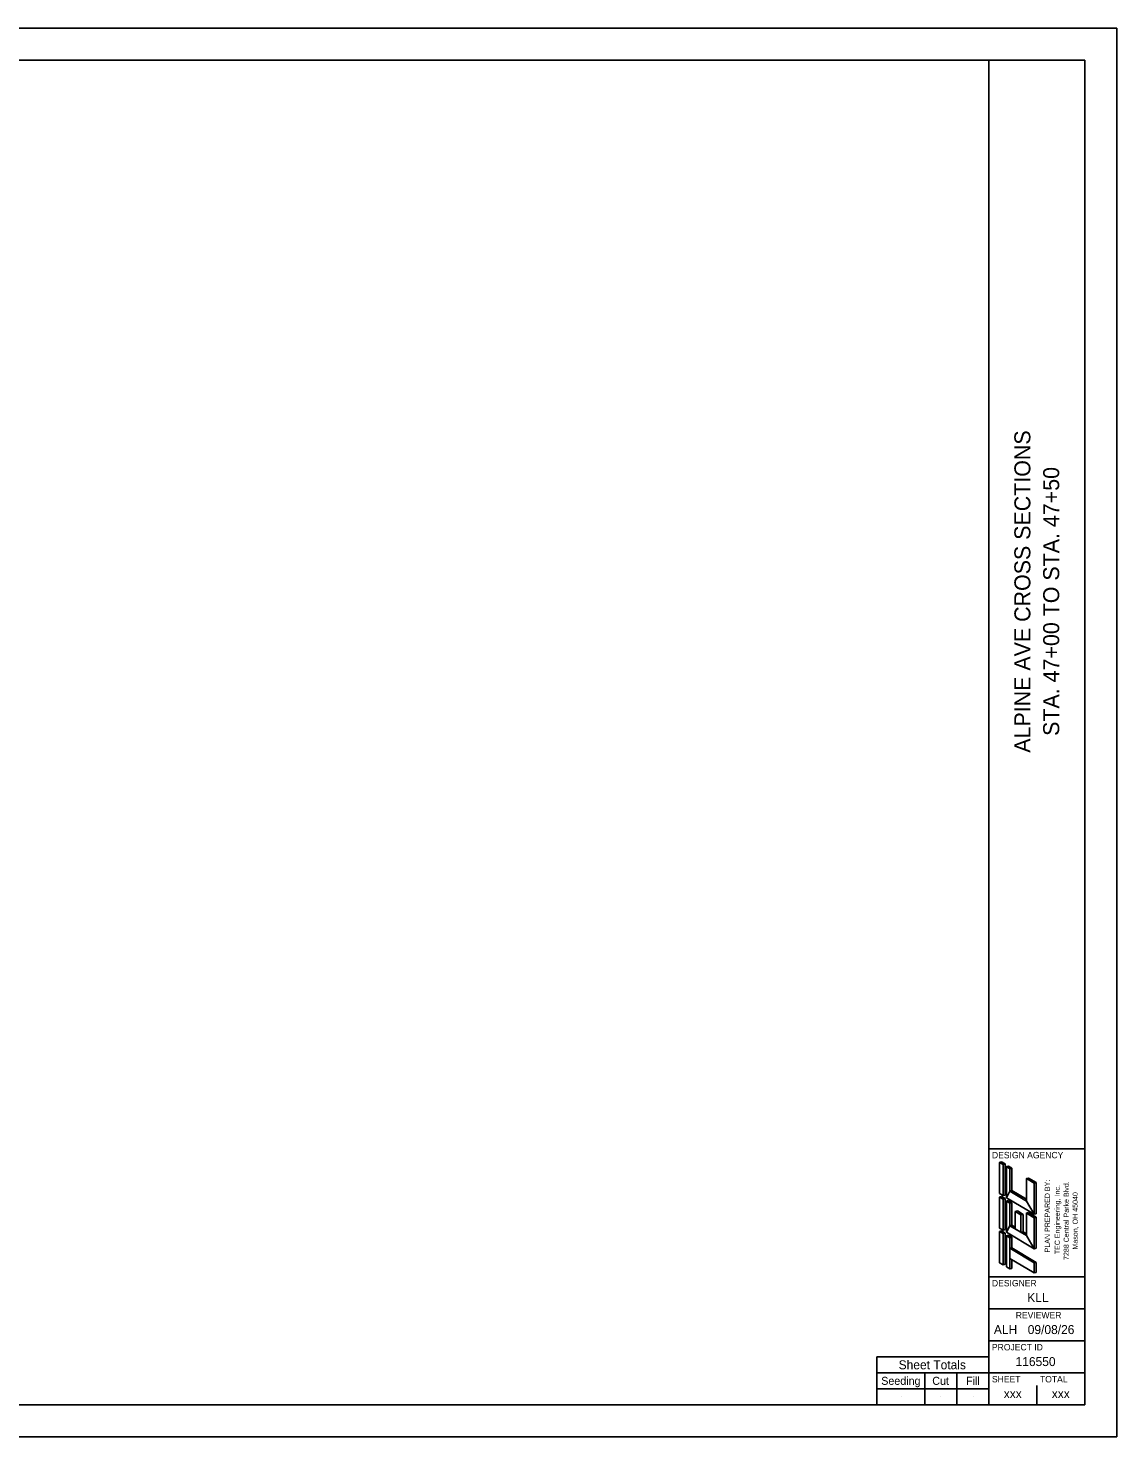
# Model space of a CAD drawing. Extents: x -32.4 to 34, y 0 to 22.
# Drawn here: x 17 to 34, y 0 to 22 of the extents above; entities that cross this region are included whole.
import ezdxf

# ---------------------------------------------------------------- set-up
doc = ezdxf.new("R2010")
doc.units = 0
for name, color, linetype in [('_CIVIL_CONSTRUCTION', 7, 'Continuous'), ('Default', 7, 'Continuous'), ('PF_X_Ground_Line', 7, 'Continuous'), ('RW_X_CL', 7, 'Continuous'), ('RW_X_CL_100_Bearings', 7, 'Continuous')]:
    doc.layers.add(name, color=color, linetype=linetype)

msp = doc.modelspace()

# ---------------------------------------------------------------- linework, layer by layer
at = {"layer": '_CIVIL_CONSTRUCTION'}
msp.add_lwpolyline([(0, 0), (34, 0), (34, 22), (0, 22)], close=True, dxfattribs=at)
at = {"layer": 'PF_X_Ground_Line'}
for p, q in [((32.75, 3.5), (32.75, 3.5)), ((30.25, 0.5), (30.25, 1.25)), ((30.25, 1.25), (32, 1.25)), ((30.25, 1), (32, 1)), ((31, 0.5), (31, 1)), ((31.5, 0.5), (31.5, 1)), ((30.25, 0.75), (32, 0.75)), ((32.375, 0.675), (32.375, 0.675)), ((32.75, 0.5), (32.75, 0.8)), ((30.632, 0.625), (30.632, 0.625)), ((31.254, 0.625), (31.254, 0.625)), ((31.76, 0.625), (31.76, 0.625))]:
    msp.add_line(p, q, dxfattribs=at)
at = {"layer": 'RW_X_CL'}
for p, q in [((32, 0.5), (32, 21.5)), ((32, 4.5), (33.5, 4.5)), ((32, 2.5), (33.5, 2.5)), ((32, 2), (33.5, 2)), ((32, 1.5), (33.5, 1.5)), ((32, 1), (33.5, 1))]:
    msp.add_line(p, q, dxfattribs=at)
msp.add_lwpolyline([(1.5, 21.5), (33.5, 21.5), (33.5, 0.5), (1.5, 0.5)], close=True, dxfattribs=at)
at = {"layer": 'RW_X_CL_100_Bearings'}
for p, q in [((32.169, 4.285), (32.201, 4.294)), ((32.169, 3.799), (32.169, 4.285)), ((32.223, 4.253), (32.169, 4.285)), ((32.255, 4.261), (32.201, 4.294)), ((32.223, 4.253), (32.255, 4.261)), ((32.223, 3.767), (32.223, 4.253)), ((32.255, 3.775), (32.255, 4.261)), ((32.277, 4.221), (32.309, 4.229)), ((32.331, 4.188), (32.277, 4.221)), ((32.277, 3.735), (32.277, 4.221)), ((32.309, 4.229), (32.363, 4.196)), ((32.331, 4.188), (32.363, 4.196)), ((32.331, 3.837), (32.331, 4.188)), ((32.363, 4.196), (32.363, 3.845)), ((32.587, 4.034), (32.62, 4.042)), ((32.587, 3.683), (32.587, 4.034)), ((32.709, 3.961), (32.587, 4.034)), ((32.62, 4.042), (32.741, 3.97)), ((32.709, 3.961), (32.741, 3.97)), ((32.709, 3.475), (32.709, 3.961)), ((32.741, 3.97), (32.741, 3.484)), ((32.223, 3.767), (32.169, 3.799)), ((32.169, 3.745), (32.201, 3.754)), ((32.169, 3.259), (32.169, 3.745)), ((32.223, 3.713), (32.169, 3.745)), ((32.255, 3.722), (32.201, 3.754)), ((32.223, 3.767), (32.255, 3.775)), ((32.331, 3.837), (32.363, 3.845)), ((32.587, 3.683), (32.331, 3.837)), ((32.363, 3.845), (32.587, 3.711)), ((32.223, 3.713), (32.255, 3.722)), ((32.223, 3.227), (32.223, 3.713)), ((32.255, 3.236), (32.255, 3.722)), ((32.709, 3.475), (32.277, 3.735)), ((32.277, 3.681), (32.309, 3.689)), ((32.277, 3.195), (32.277, 3.681)), ((32.331, 3.648), (32.277, 3.681)), ((32.309, 3.689), (32.363, 3.656)), ((32.331, 3.648), (32.363, 3.656)), ((32.331, 3.297), (32.331, 3.648)), ((32.363, 3.656), (32.363, 3.305)), ((32.415, 3.519), (32.448, 3.527)), ((32.448, 3.527), (32.535, 3.474)), ((32.331, 3.297), (32.363, 3.305)), ((32.363, 3.305), (32.415, 3.274)), ((32.415, 3.519), (32.415, 3.247)), ((32.415, 3.519), (32.503, 3.466)), ((32.503, 3.466), (32.535, 3.474)), ((32.503, 3.466), (32.503, 3.194)), ((32.535, 3.474), (32.535, 3.202)), ((32.587, 3.494), (32.62, 3.502)), ((32.587, 3.143), (32.587, 3.494)), ((32.709, 3.421), (32.587, 3.494)), ((32.62, 3.502), (32.741, 3.43)), ((32.709, 3.475), (32.741, 3.484)), ((32.709, 3.421), (32.741, 3.43)), ((32.709, 2.935), (32.709, 3.421)), ((32.741, 3.43), (32.741, 2.944)), ((32.223, 3.227), (32.169, 3.259)), ((32.169, 3.205), (32.201, 3.215)), ((32.169, 2.719), (32.169, 3.205)), ((32.223, 3.173), (32.169, 3.205)), ((32.255, 3.181), (32.201, 3.215)), ((32.222, 3.173), (32.255, 3.181)), ((32.223, 3.227), (32.255, 3.236)), ((32.223, 2.687), (32.223, 3.173)), ((32.255, 2.695), (32.255, 3.181)), ((32.709, 2.935), (32.277, 3.195)), ((32.277, 3.141), (32.309, 3.151)), ((32.331, 3.108), (32.277, 3.141)), ((32.277, 2.655), (32.277, 3.141)), ((32.309, 3.151), (32.363, 3.116)), ((32.415, 3.247), (32.331, 3.297)), ((32.331, 3.108), (32.363, 3.116)), ((32.331, 2.944), (32.331, 3.108)), ((32.363, 3.116), (32.363, 2.952)), ((32.503, 3.194), (32.535, 3.202)), ((32.587, 3.143), (32.503, 3.194)), ((32.535, 3.202), (32.587, 3.171)), ((32.331, 2.944), (32.363, 2.952)), ((32.331, 2.944), (32.709, 2.717)), ((32.363, 2.952), (32.741, 2.725)), ((32.709, 2.935), (32.741, 2.944)), ((32.223, 2.687), (32.169, 2.719)), ((32.223, 2.687), (32.255, 2.695)), ((32.331, 2.622), (32.277, 2.655)), ((32.331, 2.787), (32.709, 2.56)), ((32.331, 2.622), (32.331, 2.787)), ((32.363, 2.63), (32.363, 2.767)), ((32.709, 2.717), (32.741, 2.725)), ((32.709, 2.56), (32.709, 2.717)), ((32.741, 2.725), (32.741, 2.568)), ((32.331, 2.622), (32.363, 2.63)), ((32.709, 2.56), (32.741, 2.568))]:
    msp.add_line(p, q, dxfattribs=at)
for points in [[(32.169, 3.799), (32.223, 3.767), (32.223, 4.253), (32.169, 4.285)], [(32.277, 3.735), (32.331, 3.837), (32.331, 4.188), (32.277, 4.221)], [(32.709, 3.475), (32.587, 3.683), (32.587, 4.034), (32.709, 3.961)], [(32.169, 3.259), (32.223, 3.227), (32.223, 3.713), (32.169, 3.745)], [(32.277, 3.735), (32.331, 3.837), (32.587, 3.683), (32.709, 3.475)], [(32.277, 3.195), (32.331, 3.297), (32.331, 3.648), (32.277, 3.681)], [(32.415, 3.247), (32.415, 3.519), (32.503, 3.466), (32.503, 3.194)], [(32.709, 2.935), (32.587, 3.143), (32.587, 3.494), (32.709, 3.421)], [(32.169, 2.719), (32.223, 2.687), (32.223, 3.173), (32.169, 3.205)], [(32.277, 3.195), (32.331, 3.297), (32.587, 3.143), (32.709, 2.935)], [(32.277, 2.655), (32.331, 2.622), (32.331, 3.108), (32.277, 3.141)], [(32.331, 2.787), (32.331, 2.944), (32.709, 2.717), (32.709, 2.56)]]:
    msp.add_lwpolyline(points, close=True, dxfattribs=at)

# ---------------------------------------------------------------- texts
at = {"layer": 'Default'}
for s, p in [('PLAN PREPARED BY:', (32.954, 2.88)), ('TEC Engineering, Inc.', (33.11, 2.851)), ('7288 Central Parke Blvd.', (33.25, 2.762)), ('Mason, OH 45040', (33.39, 2.925))]:
    msp.add_text(s, height=0.08, rotation=90, dxfattribs=at).set_placement(p)
at = {"layer": 'PF_X_Ground_Line'}
for s, p in [('ALPINE AVE CROSS SECTIONS', (32.65, 10.684)), ('STA. 47+00 TO STA. 47+50', (33.1, 10.947))]:
    msp.add_text(s, height=0.25, rotation=90, dxfattribs=at).set_placement(p)
for s, height, p in [('DESIGN AGENCY', 0.1, (32.05, 4.35)), ('DESIGNER', 0.1, (32.05, 2.35)), ('KLL', 0.14, (32.601, 2.105)), ('REVIEWER', 0.1, (32.422, 1.85)), ('ALH', 0.14, (32.08, 1.605)), ('09/08/26', 0.14, (32.609, 1.605)), ('PROJECT ID', 0.1, (32.05, 1.35)), ('Sheet Totals', 0.14, (30.593, 1.055)), ('116550', 0.14, (32.419, 1.105)), ('Seeding', 0.125, (30.321, 0.812)), ('Cut', 0.125, (31.118, 0.812)), ('Fill', 0.125, (31.646, 0.812)), ('SHEET', 0.1, (32.05, 0.85)), ('TOTAL', 0.1, (32.8, 0.85)), ('xxx', 0.14, (32.234, 0.605)), ('xxx', 0.14, (32.984, 0.605))]:
    msp.add_text(s, height=height, dxfattribs=at).set_placement(p)

doc.saveas('drawing.dxf')
